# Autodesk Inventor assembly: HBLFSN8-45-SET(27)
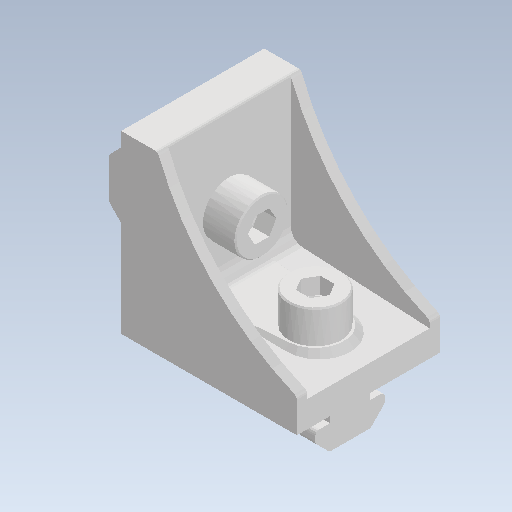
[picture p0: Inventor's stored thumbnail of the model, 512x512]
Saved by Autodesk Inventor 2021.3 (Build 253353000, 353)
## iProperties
Created: 2022-02
Part Number: HBLFSN8-45-SET(27)
Document SubType Name: Assembly
Designer: kengo
Author: kengo
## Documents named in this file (4)
- C:\Users\kengo\Documents\S2S_frame\SDC345\frame_misumi_ver12\HBLFSN8-45-SET(27).iam
- C:\Users\kengo\Documents\S2S_frame\SDC345\frame_misumi_ver12\HBLFSN8-45.ipt
- C:\Users\kengo\Documents\S2S_frame\SDC345\frame_misumi_ver12\HNTT8-8.ipt
- C:\Users\kengo\Documents\S2S_frame\SDC345\frame_misumi_ver12\CBM8-20.ipt
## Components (5 placed, 3 different names)
1. HBLFSN8-45
2. HNTT8-8
3. CBM8-20
4. HNTT8-8:1
5. CBM8-20:1
